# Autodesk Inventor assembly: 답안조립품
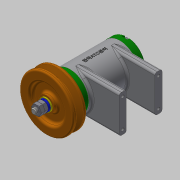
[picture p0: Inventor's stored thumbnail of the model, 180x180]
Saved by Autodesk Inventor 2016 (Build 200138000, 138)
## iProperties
Created: 2020-07
Part Number: 답안조립품
Material: 일반
Document SubType Name: Assembly
Designer: 605-15
Author: 605-15
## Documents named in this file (15)
- C:\Users\605-15\Desktop\700706V1008\답안조립품.iam
- C:\Users\605-15\Desktop\700706V1008\본체.ipt
- C:\Users\605-15\Desktop\700706V1008\축.ipt
- C:\Users\605-15\Desktop\700706V1008\베어링 6002.ipt
- C:\Users\605-15\Desktop\700706V1008\Ű 3x3x12.ipt
- C:\Users\605-15\Desktop\700706V1008\V벨트풀리.ipt
- C:\Users\605-15\Desktop\700706V1008\와셔 8x17.ipt
- C:\Users\605-15\Desktop\700706V1008\스프링와셔 8.ipt
- C:\Users\605-15\Desktop\700706V1008\너트 M8.ipt
- C:\Users\605-15\Desktop\700706V1008\앞커버.ipt
- C:\Users\605-15\Desktop\700706V1008\오일 실 15 25 7.ipt
- C:\Users\605-15\Desktop\700706V1008\뒤커버.ipt
- C:\Users\605-15\Desktop\700706V1008\볼트 M4x12.ipt
- C:\Users\605-15\Desktop\700706V1008\볼트 M6x8.ipt
- C:\Users\605-15\Desktop\700706V1008\와셔 6x11.5.ipt
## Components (2 placed, 2 different names)
1. Ű 3x3x12:1
2. V벨트풀리:1
